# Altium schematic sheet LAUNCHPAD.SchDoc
size 558 x 431 mm; Engineer: Nicholas Oborny; Revision: A.1; Name: Nicholas Oborny; Start Date: 7/23/2012
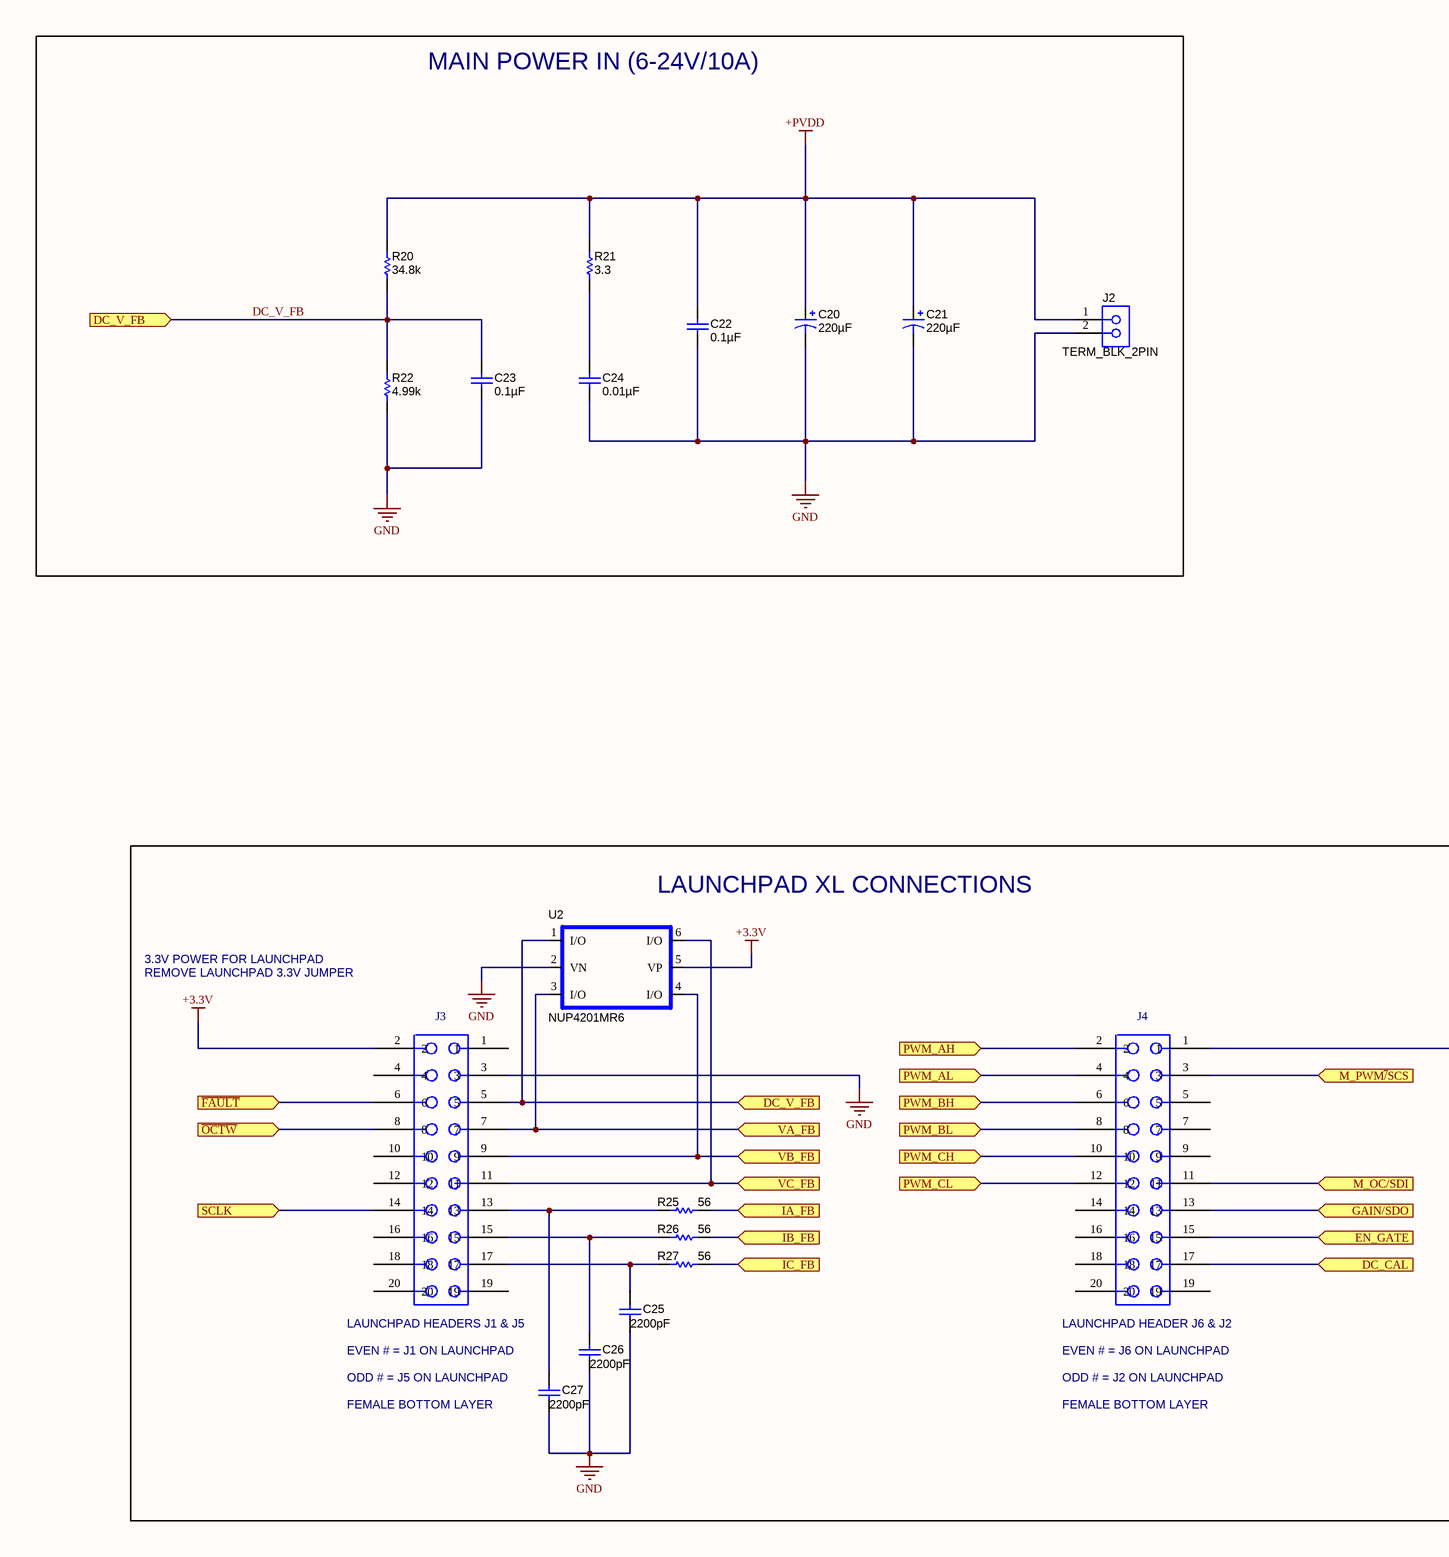
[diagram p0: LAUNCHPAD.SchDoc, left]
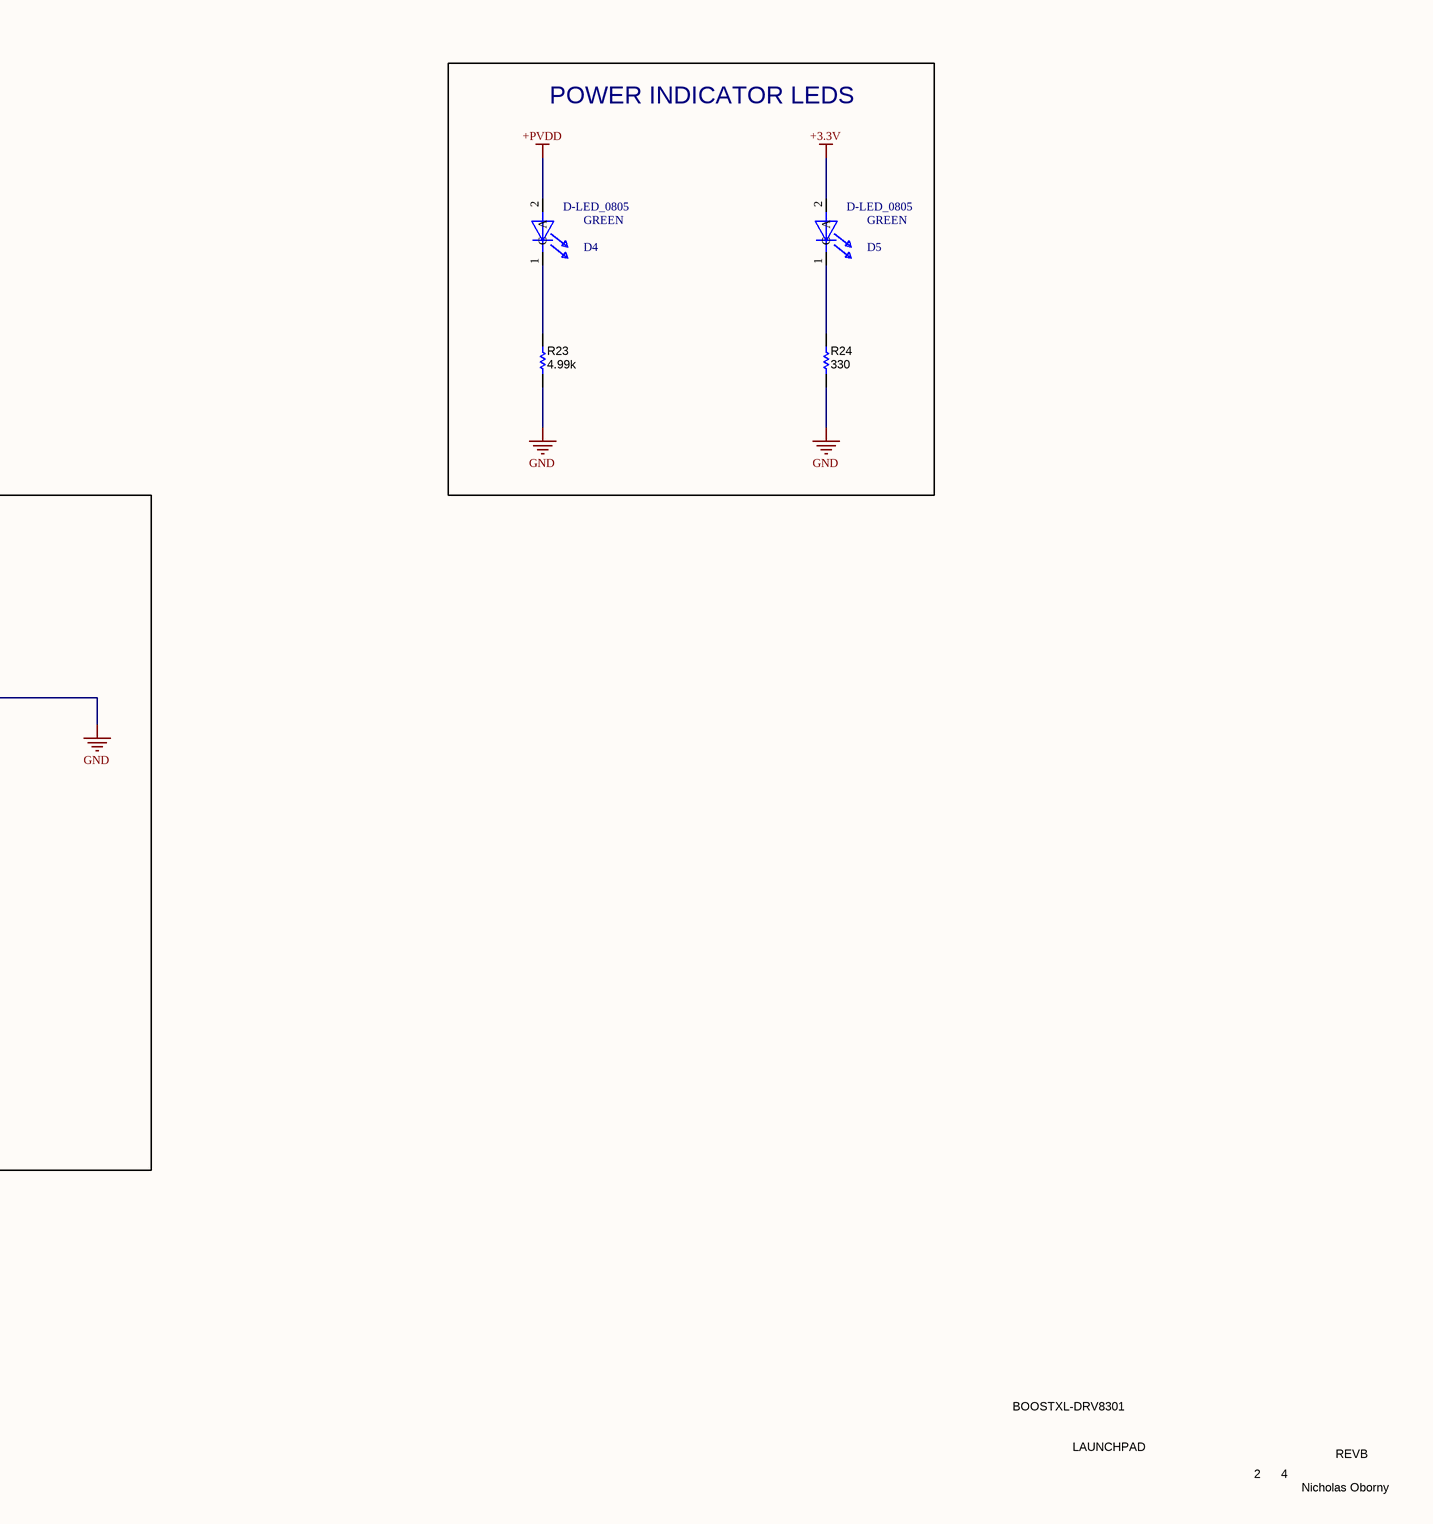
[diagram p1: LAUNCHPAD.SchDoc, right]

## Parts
C20  ValueDisplayed: 220µF  [SM_RADIAL_G]  (hidden comment: EEE-FC1H221P)
C21  ValueDisplayed: 220µF  [SM_RADIAL_G]  (hidden comment: EEE-FC1H221P)
C22  ValueDisplayed: 0.1µF  [0603L]  (hidden comment: GRM188R72A104KA35D)
C23  ValueDisplayed: 0.1µF  [0603L]  (hidden comment: C0603C104J4RACTU)
C24  ValueDisplayed: 0.01µF  [0603L]  (hidden comment: C1608X7R2A103K)
C25  ValueDisplayed: 2200pF  [0603L]  (hidden comment: GRM188R71C222KA01D)
C26  ValueDisplayed: 2200pF  [0603L]  (hidden comment: GRM188R71C222KA01D)
C27  ValueDisplayed: 2200pF  [0603L]  (hidden comment: GRM188R71C222KA01D)
D4  D-LED_0805  value GREEN  [LED_0805]
D5  D-LED_0805  value GREEN  [LED_0805]
J2  TERM_BLK_2PIN  [CONN_ED120-2DS]
J3  HEADER_NPTC202KFM  (value not drawn)
J4  HEADER_NPTC202KFM  (value not drawn)
R20  value 34.8k  [0603L]  (hidden comment: CRCW060334K8FKEA)
R21  value 3.3  [1206L]  (hidden comment: CRCW12063R30JNEA)
R22  value 4.99k  [0603L]  (hidden comment: CRCW06034K99FKEA)
R23  value 4.99k  [0603L]  (hidden comment: CRCW06034K99FKEA)
R24  value 330  [0603L]  (hidden comment: CRCW0603330RJNEA)
R25  value 56  [0603L]  (hidden comment: CRCW060356R0JNEA)
R26  value 56  [0603L]  (hidden comment: CRCW060356R0JNEA)
R27  value 56  [0603L]  (hidden comment: CRCW060356R0JNEA)
U2  NUP4201MR6  [SOT23-6]

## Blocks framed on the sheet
MAIN POWER IN (6-24V/10A): C20-C24 J2 R20-R22
POWER INDICATOR LEDS: D4 D5 R23 R24
LAUNCHPAD XL CONNECTIONS: C25-C27 J3 J4 R25-R27 U2

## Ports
DC_CAL, DC_V_FB, EN_GATE, GAIN/SDO, IA_FB, IB_FB, IC_FB, M_OC/SDI, M_PWM~{/}SCS, PWM_AH, PWM_AL, PWM_BH, PWM_BL, PWM_CH, PWM_CL, SCLK, VA_FB, VB_FB, VC_FB, ~{FAULT}, ~{OCTW}

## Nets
+3.3V: D5.2(A) J3.2 U2.5(VP)
+PVDD: C20.1(+) C21.1(+) C22.1 D4.2(A) J2.1 R20.2 R21.2
GND: C20.2(-) C21.2(-) C22.2 C23.2 C24.2 C25.2 C26.2 C27.2 J2.2 J3.3 J4.1 R22.1 R23.1 R24.1 U2.2(VN)
~{FAULT}: J3.6 ; port ~{FAULT}
~{OCTW}: J3.8 ; port ~{OCTW}
DC_CAL: J4.17 ; port DC_CAL
DC_V_FB: C23.1 J3.5 R20.1 R22.2 U2.1(I/O) ; port DC_V_FB
EN_GATE: J4.15 ; port EN_GATE
GAIN/SDO: J4.13 ; port GAIN/SDO
IA_FB: R25.2 ; port IA_FB
IB_FB: R26.2 ; port IB_FB
IC_FB: R27.2 ; port IC_FB
M_OC/SDI: J4.11 ; port M_OC/SDI
M_PWM~{/}SCS: J4.3 ; port M_PWM~{/}SCS
PWM_AH: J4.2 ; port PWM_AH
PWM_AL: J4.4 ; port PWM_AL
PWM_BH: J4.6 ; port PWM_BH
PWM_BL: J4.8 ; port PWM_BL
PWM_CH: J4.10 ; port PWM_CH
PWM_CL: J4.12 ; port PWM_CL
SCLK: J3.14 ; port SCLK
VA_FB: J3.7 U2.3(I/O) ; port VA_FB
VB_FB: J3.9 U2.4(I/O) ; port VB_FB
VC_FB: J3.11 U2.6(I/O) ; port VC_FB
NetC24_1: C24.1 R21.1
NetC25_1: C25.1 J3.17 R27.1
NetC26_1: C26.1 J3.15 R26.1
NetC27_1: C27.1 J3.13 R25.1
NetD4_1: D4.1(C) R23.2
NetD5_1: D5.1(C) R24.2

Not connected (* = marked no-connect by the designer): J3 1 4 10 12 16 18 19 20; J4 5 7 9 14 16 18 19 20

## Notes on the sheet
- 3.3V POWER FOR LAUNCHPAD
- REMOVE LAUNCHPAD 3.3V JUMPER
- (near J3) LAUNCHPAD HEADERS J1 & J5
- EVEN # = J1 ON LAUNCHPAD
- (near J4) LAUNCHPAD HEADER J6 & J2
- EVEN # = J6 ON LAUNCHPAD
- ODD # = J5 ON LAUNCHPAD
- FEMALE BOTTOM LAYER
- ODD # = J2 ON LAUNCHPAD
- BOOSTXL-DRV8301
- LAUNCHPAD
- 2
- 4
- REVB
- Nicholas Oborny

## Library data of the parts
C20 C21 = EEE-FC1H221P: CAP, AL, 220uF, 50V, +/-20%, 0.3 ohm, SMD; Manufacturer: Panasonic; Polarized: Y; CompType: Capacitor; U/M: EA; Cap_F: 0.00022; Tolerance_%: 20; Value1: 0.3 ohm; VDC_V: 50; ESR_Ohm: 0.3; IRMS_A: 0.5; TaMin_C: -40; TaMax_C: 105; Cap_Case: G
C22 = GRM188R72A104KA35D: CAP, CERM, 0.1uF, 100V, +/-10%, X7R, 0603; Manufacturer: MuRata; Polarized: N; CompType: Capacitor; U/M: EA; Cap_F: 0.0000001; Tolerance_%: 10; Value1: Unknown; VDC_V: 100; TaMin_C: -55; TaMax_C: 125; Cap_Case: 0603
C23 = C0603C104J4RACTU: CAP, CERM, 0.1uF, 16V, +/-5%, X7R, 0603; Manufacturer: Kemet; Polarized: N; CompType: Capacitor; U/M: EA; Cap_F: 0.0000001; Tolerance_%: 5; Value1: Unknown; VDC_V: 16; TaMin_C: -55; TaMax_C: 125; Cap_Case: 0603
C24 = C1608X7R2A103K: CAP, CERM, 0.01uF, 100V, +/-10%, X7R, 0603; Manufacturer: TDK; Polarized: N; CompType: Capacitor; U/M: EA; Cap_F: 0.00000001; Tolerance_%: 10; ESR_Ohm: 0.0661; Value1: 0.0661 ohm; VDC_V: 100; TaMin_C: -55; TaMax_C: 125; Cap_Case: 0603
C25-C27 = GRM188R71C222KA01D: CAP, CERM, 2200pF, 16V, +/-10%, X7R, 0603; Manufacturer: MuRata; Polarized: N; CompType: Capacitor; U/M: EA; Cap_F: 0.0000000022; Tolerance_%: 10; Value1: Unknown; VDC_V: 16; TaMin_C: -55; TaMax_C: 125; Cap_Case: 0603
D4 = D-LED_0805: LED THIN 565NM GRN DIFF 0805 SMD; PartNumber: SML-LXT0805GW-TR; Manufacturer: Lumex Opto/Components Inc; Vendor Part #: 67-1553-1-ND; Area: 2.5 mm; Vendor: DigiKey
D5 = D-LED_0805: LED THIN 565NM GRN DIFF 0805 SMD; PartNumber: SML-LXT0805GW-TR; Manufacturer: Lumex Opto/Components Inc; Vendor Part #: 67-1553-1-ND; PCB DECAL: LED-0805C; Area: 2.5 mm; Vendor: DigiKey
J2 = ED120/2DS: TERMINAL BLOCK 5.08MM VERT 2POS; PartNumber: OSTTA024163; Manufacturer: On-Shore Technology; U/M: EA; Value: 2 Pin Header
J3 J4 = HEADER_NPTC202KFM: CONN RCPT 20POS .100 DL STR SMD; PartNumber: 89898-310ALF; Manufacturer: FCI; Vendor Part #: 609-4473-1-ND; Second Source: C:\program files\p-cad 2004\HEADER_NPTC-SERIES.pdf; Reference: \\vette02\pmp_pcb\pcad_pdf's\HEADER_NPTC-SERIES.pdf; Area: 363000; Value: 20-Pin/2-Row; Vendor: DigiKey
R20 = CRCW060334K8FKEA: RES, 34.8k ohm, 1%, 0.1W, 0603; Manufacturer: Vishay-Dale; CompType: Resistor; Res_ohm: 34800; Value_Code: 34k8; Tolerance_%: 1; Power_W: 0.1; VDC_V: 75; TempCo: 100 ppm/C; EIA_Code: E96; U/M: EA
R21 = CRCW12063R30JNEA: RES, 3.3 ohm, 5%, 0.25W, 1206; Manufacturer: Vishay-Dale; CompType: Resistor; Value_Code: 3R30; Tolerance_%: 5; Power_W: 0.25; VDC_V: 200; TempCo: 200 ppm/C; EIA_Code: E24; U/M: EA
R22 R23 = CRCW06034K99FKEA: RES, 4.99k ohm, 1%, 0.1W, 0603; Manufacturer: Vishay-Dale; CompType: Resistor; Res_ohm: 4990; Value_Code: 4k99; Tolerance_%: 1; Power_W: 0.1; VDC_V: 75; TempCo: 100 ppm/C; EIA_Code: E96; U/M: EA
R24 = CRCW0603330RJNEA: RES, 330 ohm, 5%, 0.1W, 0603; Manufacturer: Vishay-Dale; CompType: Resistor; Value_Code: 330R; Tolerance_%: 5; Power_W: 0.1; VDC_V: 75; TempCo: 200 ppm/C; EIA_Code: E24; U/M: EA
R25-R27 = CRCW060356R0JNEA: RES, 56 ohm, 5%, 0.1W, 0603; Manufacturer: Vishay-Dale; CompType: Resistor; Value_Code: 56R0; Tolerance_%: 5; Power_W: 0.1; VDC_V: 75; TempCo: 200 ppm/C; EIA_Code: E24; U/M: EA
U2 = NUP4201MR6: IC,  500w 6v, Transient Voltage  Suppressors; Manufacturer: On Semi; Area: 20.1 mm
